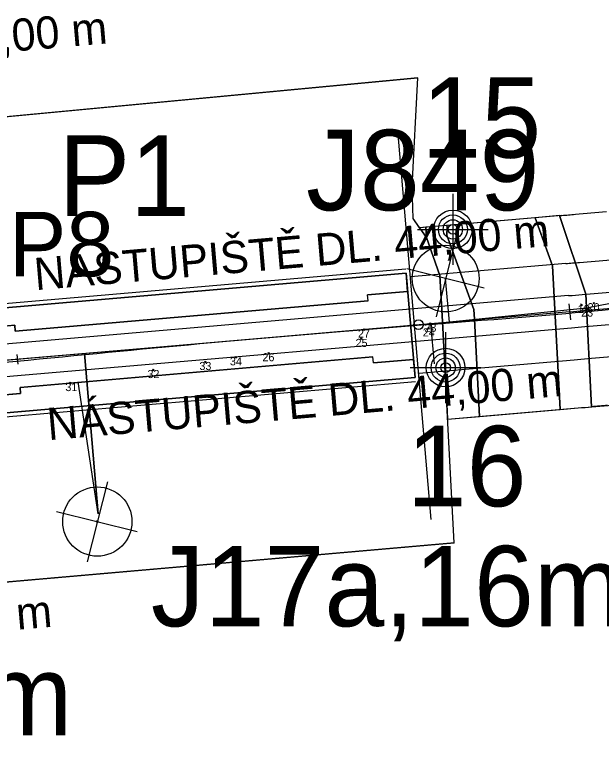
# Model space of a CAD drawing. Extents: x -606444 to -604546, y -1158114 to -1156869.
# Drawn here: x -605946.4 to -605873.5, y -1157343.8 to -1157252.5 of the extents above; entities that cross this region are included whole.
import ezdxf

# ---------------------------------------------------------------- set-up
doc = ezdxf.new("R2010")
doc.units = 0
for name, color, linetype in [('0_sondy', 7, 'Continuous'), ('ARCHIVNÍ SONDY', 7, 'Continuous'), ('B_CHOD', 7, 'Continuous'), ('B_TRAM', 7, 'Continuous'), ('B_VOZ', 7, 'Continuous'), ('B_ZELEN', 7, 'Continuous'), ('geofyzikální profily_předběžný GTP', 7, 'Continuous'), ('hydrovrty_předběžný GTP', 7, 'Continuous'), ('jádrové vrty_předběžný GTP', 7, 'Continuous'), ('korozní průzkum', 7, 'Continuous'), ('netisk', 7, 'Continuous'), ('netisk2', 7, 'Continuous'), ('NS_VB', 7, 'Continuous'), ('NS_VB_OBJ', 7, 'Continuous'), ('NS_VB_POP', 7, 'Continuous'), ('OSA', 7, 'Continuous'), ('OSAPOP', 7, 'Continuous'), ('podélný profil trasou tramvaje', 7, 'Continuous'), ('sondy předběžného průzkumu', 7, 'Continuous'), ('sondy současného průzkumu', 7, 'Continuous')]:
    doc.layers.add(name, color=color, linetype=linetype)

# ---------------------------------------------------------------- blocks, each defined once
blk = doc.blocks.new('709')
for p, q in [((0, 2.2), (0, -2.2)), ((-2.2, 0), (2.2, 0))]:
    blk.add_line(p, q)
for radius in [1.2, 0.9, 0.6, 0.3]:
    blk.add_circle((0, 0), radius)
blk = doc.blocks.new('IG vrt podr')
at = {"layer": 'sondy současného průzkumu'}
for p, q in [((0.412, 1.649), (-0.418, -1.672)), ((-1.698, 0.422), (1.644, -0.408))]:
    blk.add_line(p, q, dxfattribs=at)
blk.add_circle((-0.002, 0.001), 1.434, dxfattribs=at)
blk = doc.blocks.new('IG vrt archivní')
at = {"layer": 'sondy předběžného průzkumu'}
for p, q in [((0.406, 1.636), (-0.393, -1.584)), ((1.589, -0.397), (-1.612, 0.402))]:
    blk.add_line(p, q, dxfattribs=at)
blk.add_circle((0.001, 0.002), 1.382, dxfattribs=at)

msp = doc.modelspace()

# ---------------------------------------------------------------- linework, layer by layer
for p, q in [((-605874.446, -1157288.301), (-605874.546, -1157288.201)), ((-605874.446, -1157288.301), (-605874.346, -1157288.201)), ((-605875.992, -1157288.523), (-605876.092, -1157288.423)), ((-605875.992, -1157288.523), (-605876.092, -1157288.623)), ((-605875.992, -1157288.523), (-605875.892, -1157288.423)), ((-605875.992, -1157288.523), (-605875.892, -1157288.623)), ((-605875.295, -1157288.973), (-605875.395, -1157288.873)), ((-605875.295, -1157288.973), (-605875.395, -1157289.073)), ((-605875.295, -1157288.973), (-605875.195, -1157288.873)), ((-605875.295, -1157288.973), (-605875.195, -1157289.073)), ((-605874.446, -1157288.301), (-605874.546, -1157288.401)), ((-605874.446, -1157288.301), (-605874.346, -1157288.401)), ((-605894.77, -1157290.856), (-605894.87, -1157290.756)), ((-605894.77, -1157290.856), (-605894.87, -1157290.956)), ((-605894.77, -1157290.856), (-605894.67, -1157290.756)), ((-605894.77, -1157290.856), (-605894.67, -1157290.956)), ((-605903.022, -1157291.581), (-605903.122, -1157291.481)), ((-605903.022, -1157291.581), (-605903.122, -1157291.681)), ((-605903.022, -1157291.581), (-605902.922, -1157291.481)), ((-605903.022, -1157291.581), (-605902.922, -1157291.681)), ((-605894.964, -1157291.431), (-605895.064, -1157291.331)), ((-605894.964, -1157291.431), (-605895.064, -1157291.531)), ((-605894.964, -1157291.431), (-605894.864, -1157291.331)), ((-605894.964, -1157291.431), (-605894.864, -1157291.531)), ((-605903.323, -1157292.736), (-605903.423, -1157292.636)), ((-605903.323, -1157292.736), (-605903.423, -1157292.836)), ((-605903.323, -1157292.736), (-605903.223, -1157292.636)), ((-605903.323, -1157292.736), (-605903.223, -1157292.836)), ((-605914.865, -1157294.517), (-605914.965, -1157294.417)), ((-605914.865, -1157294.517), (-605914.965, -1157294.617)), ((-605914.865, -1157294.517), (-605914.765, -1157294.417)), ((-605914.865, -1157294.517), (-605914.765, -1157294.617)), ((-605922.728, -1157295.602), (-605922.828, -1157295.502)), ((-605922.728, -1157295.602), (-605922.628, -1157295.502)), ((-605918.934, -1157295.026), (-605919.034, -1157294.926)), ((-605918.934, -1157295.026), (-605919.034, -1157295.126)), ((-605918.934, -1157295.026), (-605918.834, -1157294.926)), ((-605918.934, -1157295.026), (-605918.834, -1157295.126)), ((-605922.728, -1157295.602), (-605922.828, -1157295.702)), ((-605922.728, -1157295.602), (-605922.628, -1157295.702)), ((-605929.177, -1157296.609), (-605929.277, -1157296.509)), ((-605929.177, -1157296.609), (-605929.277, -1157296.709)), ((-605929.177, -1157296.609), (-605929.077, -1157296.509)), ((-605929.177, -1157296.609), (-605929.077, -1157296.709)), ((-605939.501, -1157298.227), (-605939.601, -1157298.127)), ((-605939.501, -1157298.227), (-605939.601, -1157298.327)), ((-605939.501, -1157298.227), (-605939.401, -1157298.127)), ((-605939.501, -1157298.227), (-605939.401, -1157298.327)), ((-605936.135, -1157315.439), (-605936.235, -1157315.539)), ((-605936.135, -1157315.439), (-605936.035, -1157315.339)), ((-605936.135, -1157315.439), (-605936.035, -1157315.539))]:
    msp.add_line(p, q)
at = {"layer": 'B_CHOD'}
for points in [[(-605897.784, -1157284.592), (-605952.943, -1157289.341), (-605955.932, -1157289.599), (-605956.929, -1157289.684), (-606027.507, -1157276.731), (-606027.349, -1157279.81), (-605959.865, -1157292.196), (-605946.41, -1157291.037), (-605946.346, -1157291.784), (-605902.508, -1157288.01), (-605902.572, -1157287.263), (-605897.591, -1157286.834), (-605897.784, -1157284.592)], [(-605874.749, -1157301.177), (-605875.462, -1157287.187), (-605878.694, -1157277.428), (-605881.729, -1157277.689), (-605879.591, -1157283.653), (-605878.647, -1157301.513), (-605876.383, -1157301.318)], [(-605889.34, -1157289.1), (-605892.71, -1157279.86), (-605892.69, -1157278.84), (-605892.7, -1157278.634), (-605895.331, -1157278.861), (-605895.26, -1157280.16), (-605893.57, -1157284.85), (-605893.25, -1157290.57), (-605892.72, -1157300.84), (-605892.621, -1157302.716), (-605888.653, -1157302.374), (-605889.28, -1157290.28), (-605889.34, -1157289.1)], [(-605955.813, -1157302.636), (-605954.817, -1157302.551), (-605951.828, -1157302.293), (-605896.668, -1157297.544), (-605896.861, -1157295.302), (-605901.843, -1157295.731), (-605901.907, -1157294.984), (-605945.745, -1157298.759), (-605945.681, -1157299.506), (-605959.944, -1157300.734), (-606025.286, -1157320.141), (-606025.128, -1157323.224), (-605955.813, -1157302.636)]]:
    msp.add_lwpolyline(points, dxfattribs=at)
msp.add_arc((-606550.478, -1149468.865), 7861.407, 274.9190044, 274.9309584, dxfattribs=at)
at = {"layer": 'B_TRAM'}
for p, q in [((-605902.572, -1157287.263), (-605897.591, -1157286.834)), ((-605902.508, -1157288.01), (-605902.572, -1157287.263)), ((-605897.591, -1157286.834), (-605896.861, -1157295.302)), ((-605946.346, -1157291.784), (-605902.508, -1157288.01)), ((-605946.41, -1157291.037), (-605946.346, -1157291.784)), ((-605901.907, -1157294.984), (-605945.745, -1157298.759)), ((-605901.843, -1157295.731), (-605901.907, -1157294.984)), ((-605896.861, -1157295.302), (-605901.843, -1157295.731)), ((-605945.745, -1157298.759), (-605945.681, -1157299.506)), ((-605945.681, -1157299.506), (-605959.944, -1157300.734))]:
    msp.add_line(p, q, dxfattribs=at)
at = {"layer": 'B_VOZ'}
for p, q in [((-605881.729, -1157277.689), (-605892.7, -1157278.634)), ((-605879.591, -1157283.653), (-605881.729, -1157277.689)), ((-605892.69, -1157278.84), (-605892.71, -1157279.86)), ((-605892.7, -1157278.634), (-605892.69, -1157278.84)), ((-605892.71, -1157279.86), (-605889.34, -1157289.1)), ((-605878.647, -1157301.513), (-605879.591, -1157283.653)), ((-605889.34, -1157289.1), (-605889.28, -1157290.28)), ((-605889.28, -1157290.28), (-605888.653, -1157302.374)), ((-605888.653, -1157302.374), (-605878.647, -1157301.513))]:
    msp.add_line(p, q, dxfattribs=at)
at = {"layer": 'B_ZELEN'}
for p, q in [((-605878.694, -1157277.428), (-605878.441, -1157277.406)), ((-605875.462, -1157287.187), (-605878.694, -1157277.428)), ((-605874.749, -1157301.177), (-605875.462, -1157287.187))]:
    msp.add_line(p, q, dxfattribs=at)
for points in [[(-605896.3, -1157260.32), (-605954.966, -1157265.85), (-605952.943, -1157289.341), (-605897.784, -1157284.592), (-605896.668, -1157297.544), (-605951.828, -1157302.293), (-605950.029, -1157323.188), (-605891.821, -1157318.079), (-605892.14, -1157311.81), (-605892.72, -1157300.84), (-605893.25, -1157290.57), (-605893.57, -1157284.85), (-605895.26, -1157280.16), (-605896.88, -1157277.8), (-605897.04, -1157273.82), (-605896.3, -1157260.32)], [(-605895.331, -1157278.861), (-605896.106, -1157278.927), (-605895.26, -1157280.16), (-605895.331, -1157278.861)]]:
    msp.add_lwpolyline(points, dxfattribs=at)
for centre, radius, start, end in [((-606060.122, -1155151.967), 2133.189, 274.931445, 275.036025), ((-606550.479, -1149468.858), 7837.414, 274.9190013, 274.9314453), ((-605826.763, -1157853.755), 554.658, 94.75641, 94.96312)]:
    msp.add_arc(centre, radius, start, end, dxfattribs=at)
at = {"layer": 'geofyzikální profily_předběžný GTP'}
msp.add_spline([(-605950.45, -1157295.92), (-605904.874, -1157291.719), (-605856.97, -1157287.385), (-605826.739, -1157281.637), (-605800.72, -1157271.737), (-605782.37, -1157261.31), (-605766.27, -1157249.354), (-605744.492, -1157228.624), (-605716.536, -1157200.554), (-605701.175, -1157186.191), (-605682.489, -1157172.855), (-605668.895, -1157164.852), (-605653.702, -1157158.019), (-605640.639, -1157153.348), (-605624.44, -1157148.581)], degree=3, dxfattribs=at)
at = {"layer": 'hydrovrty_předběžný GTP'}
msp.add_line((-605936.135, -1157315.439), (-605936.235, -1157315.339), dxfattribs=at)
at = {"layer": 'netisk'}
for p, q in [((-605892.372, -1157290.643), (-605892.86, -1157285.252)), ((-605894.74, -1157290.857), (-605894.29, -1157295.834)), ((-605937.733, -1157294.556), (-605936.02, -1157314.456)), ((-605936.02, -1157314.456), (-605938.519, -1157298.055))]:
    msp.add_line(p, q, dxfattribs=at)
at = {"layer": 'netisk2'}
msp.add_line((-605936.02, -1157314.456), (-605937.733, -1157294.556), dxfattribs=at)
at = {"layer": 'NS_VB'}
for p, q in [((-605954.966, -1157265.85), (-605896.3, -1157260.32)), ((-605897.04, -1157273.82), (-605896.3, -1157260.32)), ((-605896.88, -1157277.8), (-605897.04, -1157273.82)), ((-605896.106, -1157278.927), (-605896.88, -1157277.8)), ((-605878.441, -1157277.406), (-605896.106, -1157278.927)), ((-605881.729, -1157277.689), (-605879.591, -1157283.653)), ((-605879.591, -1157283.653), (-605881.729, -1157277.689)), ((-605878.694, -1157277.428), (-605875.462, -1157287.187)), ((-605895.331, -1157278.861), (-605895.26, -1157280.16)), ((-605892.71, -1157279.86), (-605892.69, -1157278.84)), ((-605892.69, -1157278.84), (-605892.7, -1157278.634)), ((-605889.34, -1157289.1), (-605892.71, -1157279.86)), ((-605893.57, -1157284.85), (-605895.26, -1157280.16)), ((-605878.647, -1157301.513), (-605879.591, -1157283.653)), ((-605897.784, -1157284.592), (-605956.929, -1157289.684)), ((-605896.668, -1157297.544), (-605897.784, -1157284.592)), ((-605893.25, -1157290.57), (-605893.57, -1157284.85)), ((-605897.591, -1157286.834), (-605902.572, -1157287.263)), ((-605902.508, -1157288.01), (-605902.572, -1157287.263)), ((-605875.462, -1157287.187), (-605874.749, -1157301.177)), ((-605889.28, -1157290.28), (-605889.34, -1157289.1)), ((-605892.72, -1157300.84), (-605893.25, -1157290.57)), ((-605888.653, -1157302.374), (-605889.28, -1157290.28)), ((-605946.41, -1157291.037), (-605959.865, -1157292.196)), ((-605946.346, -1157291.784), (-605946.41, -1157291.037)), ((-605901.843, -1157295.731), (-605901.907, -1157294.984)), ((-605901.843, -1157295.731), (-605896.861, -1157295.302)), ((-605955.813, -1157302.636), (-605896.668, -1157297.544)), ((-605951.287, -1157302.749), (-605896.626, -1157298.042)), ((-605945.681, -1157299.506), (-605945.745, -1157298.759)), ((-605959.944, -1157300.734), (-605945.681, -1157299.506)), ((-605892.14, -1157311.81), (-605892.72, -1157300.84)), ((-605891.821, -1157318.079), (-605892.14, -1157311.81)), ((-605891.782, -1157318.075), (-606025.194, -1157329.785))]:
    msp.add_line(p, q, dxfattribs=at)
for points in [[(-605902.508, -1157288.01), (-605946.346, -1157291.784)], [(-605945.745, -1157298.759), (-605901.907, -1157294.984)], [(-605892.621, -1157302.716), (-605876.383, -1157301.318)]]:
    msp.add_lwpolyline(points, dxfattribs=at)
for centre, radius, start, end in [((-605975.45, -1156122.953), 1158.52, 274.887453, 275.080017), ((-606550.48, -1149468.838), 7837.434, 274.9190013, 274.9314453), ((-605975.45, -1156122.953), 1182.52, 274.887902, 275.279274), ((-606550.478, -1149468.865), 7861.407, 274.9190044, 274.9313785)]:
    msp.add_arc(centre, radius, start, end, dxfattribs=at)
at = {"layer": 'NS_VB_OBJ'}
msp.add_line((-605877.927, -1157283.384), (-605897.243, -1157285.047), dxfattribs=at)
for points in [[(-605894.648, -1157315.186), (-605898.808, -1157266.865)], [(-605897.827, -1157284.094), (-605952.488, -1157288.8), (-605953.409, -1157278.1)], [(-605896.213, -1157297.003), (-605876.897, -1157295.34)]]:
    msp.add_lwpolyline(points, dxfattribs=at)
for centre, radius, start, end in [((-606550.479, -1149468.854), 7843.418, 274.9190021, 274.9314285), ((-605975.45, -1156122.953), 1164.52, 274.887567, 275.080017), ((-606550.479, -1149468.856), 7855.416, 274.9190037, 274.9313951), ((-605975.45, -1156122.953), 1176.52, 274.887791, 275.078396)]:
    msp.add_arc(centre, radius, start, end, dxfattribs=at)
at = {"layer": 'OSA'}
msp.add_line((-605877.412, -1157289.362), (-606018.006, -1157301.467), dxfattribs=at)
for points in [[(-605877.584, -1157287.369), (-606018.177, -1157299.475)], [(-606017.835, -1157303.46), (-605877.241, -1157291.355)]]:
    msp.add_lwpolyline(points, dxfattribs=at)
for centre, radius, start, end in [((-606550.48, -1149468.839), 7847.433, 274.9190026, 274.9314174), ((-605975.45, -1156122.953), 1168.52, 274.887642, 275.279274), ((-605975.45, -1156122.953), 1170.52, 274.887679, 275.279274), ((-606550.479, -1149468.854), 7849.418, 274.9190029, 274.9314118), ((-605975.45, -1156122.953), 1172.52, 274.887717, 275.279274), ((-606550.48, -1149468.847), 7851.425, 274.9190032, 274.9314062)]:
    msp.add_arc(centre, radius, start, end, dxfattribs=at)
at = {"layer": 'OSAPOP'}
for p, q in [((-605877.326, -1157290.358), (-605877.498, -1157288.366)), ((-605945.994, -1157295.869), (-605946.097, -1157294.674))]:
    msp.add_line(p, q, dxfattribs=at)
msp.add_circle((-605896.23, -1157290.982), 0.6, dxfattribs=at)
at = {"layer": 'podélný profil trasou tramvaje'}
msp.add_lwpolyline([(-605949.772, -1157295.552), (-605894.77, -1157290.856), (-605875.375, -1157288.893), (-605864.92, -1157286.84), (-605852.13, -1157285.48)], dxfattribs=at)

# ---------------------------------------------------------------- block references
at = {"layer": '0_sondy', "xscale": 2, "yscale": 2}
for p in [(-605891.965, -1157279.136), (-605892.869, -1157296.31)]:
    msp.add_blockref('709', p, dxfattribs=at)
at = {"layer": 'ARCHIVNÍ SONDY', "xscale": 3, "yscale": 3}
msp.add_blockref('IG vrt archivní', (-605892.86, -1157285.252), dxfattribs=at)
at = {"layer": 'jádrové vrty_předběžný GTP', "xscale": 3, "yscale": 3}
msp.add_blockref('IG vrt podr', (-605936.135, -1157315.439), dxfattribs=at)

# ---------------------------------------------------------------- texts
for s, p in [('19', (-605876.445, -1157289.523)), ('23', (-605876.027, -1157289.973)), ('20', (-605875.222, -1157289.301)), ('28', (-605895.502, -1157291.856)), ('27', (-605903.754, -1157292.581)), ('24', (-605895.696, -1157292.431)), ('25', (-605904.055, -1157293.736)), ('26', (-605915.625, -1157295.517)), ('34', (-605919.666, -1157296.026)), ('33', (-605923.46, -1157296.602)), ('32', (-605929.909, -1157297.609)), ('31', (-605940.115, -1157299.227))]:
    msp.add_text(s, height=1).set_placement(p)
at = {"layer": '0_sondy'}
for s, p in [('15', (-605895.863, -1157270.231)), ('16', (-605897.687, -1157313.54))]:
    msp.add_text(s, height=10, dxfattribs=at).set_placement(p)
at = {"layer": 'ARCHIVNÍ SONDY'}
msp.add_text('J849', height=10, dxfattribs=at).set_placement((-605910.207, -1157276.768))
at = {"layer": 'geofyzikální profily_předběžný GTP'}
msp.add_text('P1', height=10, dxfattribs=at).set_placement((-605940.979, -1157277.46))
at = {"layer": 'jádrové vrty_předběžný GTP'}
for s, p in [('J17a,16m', (-605929.488, -1157328.448)), ('J17,15m', (-605990.531, -1157341.987))]:
    msp.add_text(s, height=10, dxfattribs=at).set_placement(p)
at = {"layer": 'korozní průzkum'}
msp.add_text('BP8', height=8, dxfattribs=at).set_placement((-605954.271, -1157284.961))
at = {"layer": 'NS_VB_POP'}
for s, p in [('OPĚRNÁ ZEĎ DL. 150,00 m', (-606002.891, -1157261.89)), ('NÁSTUPIŠTĚ DL. 44,00 m', (-605943.819, -1157286.699)), ('NÁSTUPIŠTĚ DL. 44,00 m', (-605942.215, -1157305.33)), ('OPĚRNÁ ZEĎ DL. 150,00 m', (-606009.761, -1157334.362))]:
    msp.add_text(s, height=4, rotation=4.92107, dxfattribs=at).set_placement(p)

doc.saveas('drawing.dxf')
